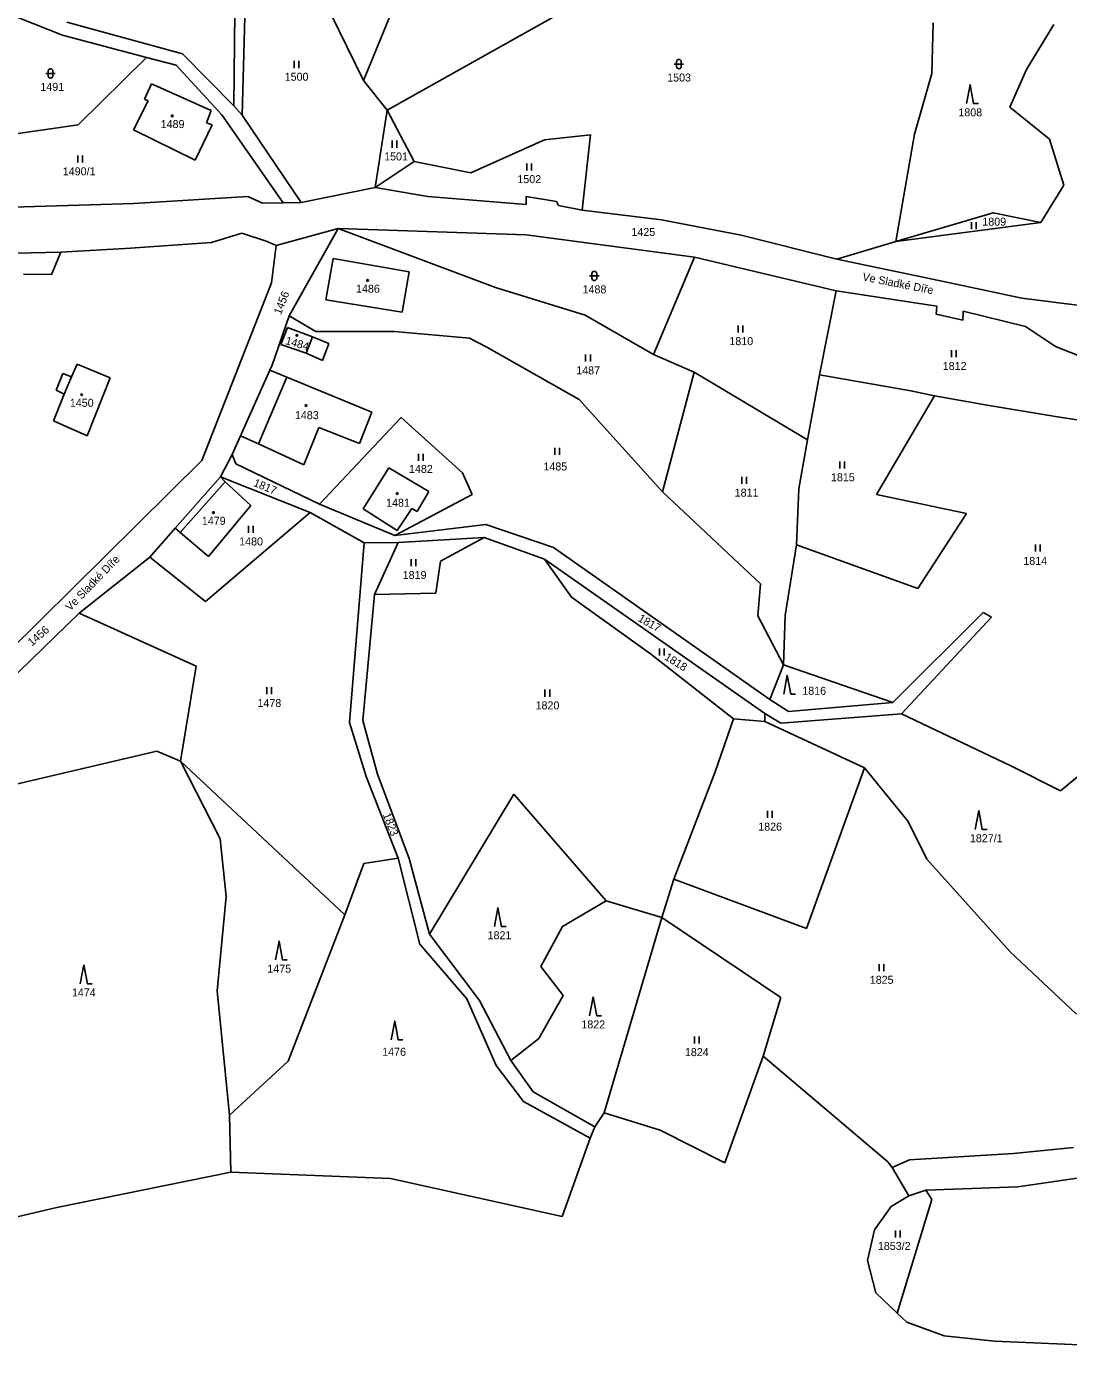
# Model space of a CAD drawing. Extents: x -670359 to -668019, y -978807 to -976674.
# Drawn here: x -669122.6 to -668901.2, y -978796.6 to -978516 of the extents above; entities that cross this region are included whole.
import ezdxf

# ---------------------------------------------------------------- set-up
doc = ezdxf.new("R2010")
doc.units = 0
for name, color, linetype in [('Hranice kat_území', 7, 'Continuous'), ('Hranice parcel', 7, 'Continuous'), ('Parcelní čísla', 7, 'Continuous'), ('Pop  PČ popisy', 7, 'Continuous'), ('Vnitřní kresba', 7, 'Continuous'), ('Značky budov', 7, 'Continuous'), ('Značky kultur', 7, 'Continuous')]:
    doc.layers.add(name, color=color, linetype=linetype)

msp = doc.modelspace()

# ---------------------------------------------------------------- linework, layer by layer
at = {"layer": 'Hranice kat_území'}
for points in [[(-668974.22, -978757.37), (-668966.07, -978734.72)], [(-668966.07, -978734.72), (-668939.56, -978757.11)], [(-669001.78, -978749.69), (-668999.81, -978746.76)], [(-668999.81, -978746.76), (-668987.95, -978750.41)], [(-669002.79, -978752.15), (-669001.78, -978749.69)], [(-668987.95, -978750.41), (-668974.22, -978757.37)], [(-669008.76, -978768.77), (-669002.79, -978752.15)], [(-669116.14, -978766.86), (-669079.11, -978759.37)], [(-669079.11, -978759.37), (-669045.2, -978760.68)], [(-668939.56, -978757.11), (-668938.62, -978758.32)], [(-668938.62, -978758.32), (-668935.12, -978764.38)], [(-669045.2, -978760.68), (-669008.76, -978768.77)], [(-668935.12, -978764.38), (-668938.85, -978766.64)], [(-669129.14, -978769.92), (-669116.14, -978766.86)], [(-668938.85, -978766.64), (-668942.37, -978771.62)], [(-668942.37, -978771.62), (-668943.85, -978778.07)], [(-668943.85, -978778.07), (-668942.12, -978784.98)], [(-668942.12, -978784.98), (-668937.55, -978789.26)], [(-668935.51, -978791.17), (-668937.55, -978789.26)], [(-668935.51, -978791.17), (-668927.63, -978794.11)], [(-668927.63, -978794.11), (-668916.93, -978795.26)], [(-668916.93, -978795.26), (-668885.55, -978796.6)]]:
    msp.add_lwpolyline(points, dxfattribs=at)
at = {"layer": 'Hranice parcel'}
for points in [[(-669050.94, -978527.45), (-669069.9, -978488.77)], [(-669037.87, -978495.52), (-669050.94, -978527.45)], [(-669078.25, -978506.04), (-669078.53, -978532.83)], [(-669075.93, -978506.06), (-669076.71, -978534.85)], [(-669132.89, -978510.73), (-669114.87, -978517.8)], [(-669113.97, -978515.09), (-669089.38, -978521.76)], [(-669008.9, -978513.02), (-669045.91, -978533.73)], [(-668929.94, -978515.21), (-668930.2, -978525.93)], [(-669114.87, -978517.8), (-669097.05, -978522.55)], [(-668910.1, -978525.08), (-668904.33, -978515.58)], [(-669111.55, -978536.87), (-669097.05, -978522.55)], [(-669097.05, -978522.55), (-669090.77, -978524.22)], [(-669089.38, -978521.76), (-669078.53, -978532.83)], [(-669090.77, -978524.22), (-669081.03, -978534.72)], [(-668930.2, -978525.93), (-668933.87, -978538.82)], [(-668913.68, -978533.1), (-668910.1, -978525.08)], [(-669097.49, -978531.43), (-669096.01, -978528.16)], [(-669096.01, -978528.16), (-669083.35, -978533.82)], [(-669045.91, -978533.73), (-669050.94, -978527.45)], [(-669099.8, -978537.96), (-669096.69, -978531.75)], [(-669096.69, -978531.75), (-669097.49, -978531.43)], [(-669083.35, -978533.82), (-669084.29, -978536.41)], [(-669081.03, -978534.72), (-669068.02, -978553.42)], [(-669078.53, -978532.83), (-669076.71, -978534.85)], [(-669076.71, -978534.85), (-669064.18, -978553.38)], [(-669048.49, -978550.2), (-669045.91, -978533.73)], [(-669045.91, -978533.73), (-669040.18, -978544.63)], [(-668905.23, -978539.89), (-668913.68, -978533.1)], [(-669125.82, -978538.9), (-669111.55, -978536.87)], [(-669083.1, -978536.9), (-669086.74, -978544.38)], [(-669084.29, -978536.41), (-669083.1, -978536.9)], [(-669086.74, -978544.38), (-669099.8, -978537.96)], [(-669028.14, -978547.08), (-669012.49, -978540.08)], [(-669012.49, -978540.08), (-669002.7, -978538.97)], [(-669002.7, -978538.97), (-669004.5, -978555.02)], [(-668933.87, -978538.82), (-668937.86, -978561.63)], [(-668902.2, -978549.7), (-668905.23, -978539.89)], [(-669040.18, -978544.63), (-669048.49, -978550.2)], [(-669040.18, -978544.63), (-669028.14, -978547.08)], [(-669048.49, -978550.2), (-669064.18, -978553.38)], [(-669037.27, -978552.07), (-669048.49, -978550.2)], [(-668907.06, -978557.61), (-668902.2, -978549.7)], [(-669099.72, -978553.56), (-669137.18, -978554.7)], [(-669075.53, -978552.06), (-669099.72, -978553.56)], [(-669072.43, -978553.53), (-669075.53, -978552.06)], [(-669068.02, -978553.42), (-669072.43, -978553.53)], [(-669064.18, -978553.38), (-669068.02, -978553.42)], [(-669016.4, -978553.82), (-669037.27, -978552.07)], [(-669016.38, -978552.06), (-669016.4, -978553.82)], [(-669009.99, -978553.17), (-669016.38, -978552.06)], [(-669009.51, -978553.97), (-669009.99, -978553.17)], [(-669004.5, -978555.02), (-669009.51, -978553.97)], [(-669004.5, -978555.02), (-668987.68, -978557.05)], [(-668970.7, -978560.28), (-668987.68, -978557.05)], [(-668937.86, -978561.63), (-668917.19, -978555.59)], [(-668917.19, -978555.59), (-668907.06, -978557.61)], [(-669076.82, -978559.88), (-669083.24, -978561.89)], [(-669071.39, -978561.62), (-669076.82, -978559.88)], [(-669056.35, -978558.88), (-669069.48, -978562.52)], [(-669056.35, -978558.88), (-669066.76, -978577.43)], [(-669016.38, -978560.22), (-669056.35, -978558.88)], [(-669056.35, -978558.88), (-669022.91, -978571.42)], [(-668937.86, -978561.63), (-668907.06, -978557.61)], [(-669083.24, -978561.89), (-669100.46, -978563.07)], [(-669069.48, -978562.52), (-669071.39, -978561.62)], [(-669069.48, -978562.52), (-669070.52, -978570.43)], [(-668980.66, -978564.96), (-669016.38, -978560.22)], [(-668950.41, -978565.41), (-668970.7, -978560.28)], [(-668950.41, -978565.41), (-668937.86, -978561.63)], [(-669115.28, -978563.95), (-669124.89, -978564.16)], [(-669100.46, -978563.07), (-669115.28, -978563.95)], [(-669058.96, -978574.07), (-669057.42, -978565.29)], [(-669057.42, -978565.29), (-669041.28, -978568.11)], [(-668980.66, -978564.96), (-668989.34, -978585.68)], [(-668950.53, -978572.13), (-668980.66, -978564.96)], [(-668927.36, -978570.21), (-668950.41, -978565.41)], [(-669041.28, -978568.11), (-669042.73, -978576.65)], [(-669070.52, -978570.43), (-669085.33, -978608.18)], [(-669022.91, -978571.42), (-669003.84, -978577.31)], [(-668911.1, -978573.7), (-668927.36, -978570.21)], [(-669042.73, -978576.65), (-669058.96, -978574.07)], [(-668950.53, -978572.13), (-668954.08, -978589.98)], [(-668929.14, -978575.38), (-668950.53, -978572.13)], [(-668898.72, -978575.28), (-668911.1, -978573.7)], [(-668929.32, -978577.06), (-668929.14, -978575.38)], [(-668923.55, -978576.44), (-668923.66, -978578.36)], [(-668910.32, -978579.71), (-668923.55, -978576.44)], [(-669066.76, -978577.43), (-669070.39, -978587.95)], [(-669066.76, -978577.43), (-669061.11, -978580.77)], [(-669003.84, -978577.31), (-668989.34, -978585.68)], [(-668923.66, -978578.36), (-668929.32, -978577.06)], [(-668903.91, -978583.99), (-668910.32, -978579.71)], [(-669068.5, -978583.53), (-669067.1, -978579.94)], [(-669067.1, -978579.94), (-669061.76, -978581.88)], [(-669061.76, -978581.88), (-669058.34, -978583.31)], [(-669061.11, -978580.77), (-669044.38, -978580.79)], [(-669044.38, -978580.79), (-669028.46, -978582.16)], [(-669028.46, -978582.16), (-669024.72, -978584.12)], [(-669063.16, -978585.39), (-669068.5, -978583.53)], [(-669063.16, -978585.39), (-669059.69, -978586.9)], [(-669058.34, -978583.31), (-669059.69, -978586.9)], [(-669024.72, -978584.12), (-669005.15, -978595.21)], [(-668897.87, -978586.33), (-668903.91, -978583.99)], [(-669113, -978590.37), (-669111.77, -978587.74)], [(-669111.77, -978587.74), (-669104.76, -978590.62)], [(-669070.39, -978587.95), (-669070.84, -978588.96)], [(-668989.34, -978585.68), (-668980.68, -978589.43)], [(-669116.23, -978593.21), (-669114.83, -978589.71)], [(-669114.83, -978589.71), (-669113, -978590.37)], [(-669104.76, -978590.62), (-669109.69, -978602.96)], [(-669070.84, -978588.96), (-669077.06, -978602.9)], [(-669070.84, -978588.96), (-669067.21, -978590.46)], [(-669067.21, -978590.46), (-669049.2, -978597.93)], [(-668980.68, -978589.43), (-668987.45, -978614.83)], [(-668956.6, -978603.78), (-668980.68, -978589.43)], [(-668954.08, -978589.98), (-668956.6, -978603.78)], [(-668934.65, -978593.36), (-668954.08, -978589.98)], [(-669114.56, -978594.11), (-669116.23, -978593.21)], [(-668929.62, -978594.41), (-668934.65, -978593.36)], [(-669116.78, -978599.76), (-669114.56, -978594.11)], [(-669005.15, -978595.21), (-668987.45, -978614.83)], [(-668929.62, -978594.41), (-668941.99, -978615.39)], [(-668918.45, -978596.45), (-668929.62, -978594.41)], [(-668903.93, -978598.79), (-668918.45, -978596.45)], [(-669060.29, -978617.45), (-669042.97, -978599.04)], [(-669049.2, -978597.93), (-669051.83, -978604.54)], [(-669042.97, -978599.04), (-669029.94, -978610.79)], [(-668890.24, -978600.95), (-668903.93, -978598.79)], [(-669109.69, -978602.96), (-669116.78, -978599.76)], [(-669060.44, -978601.17), (-669063.65, -978609.06)], [(-669051.83, -978604.54), (-669060.44, -978601.17)], [(-669077.06, -978602.9), (-669078.83, -978606.89)], [(-669073.29, -978604.63), (-669077.06, -978602.9)], [(-669063.65, -978609.06), (-669073.29, -978604.63)], [(-668956.6, -978603.78), (-668958.46, -978614.22)], [(-669078.83, -978606.89), (-669081.37, -978611.66)], [(-669078.83, -978606.89), (-669078.05, -978608.9)], [(-669085.33, -978608.18), (-669147.05, -978669.18)], [(-669078.05, -978608.9), (-669060.29, -978617.45)], [(-669051.02, -978618.47), (-669045.56, -978609.73)], [(-669045.56, -978609.73), (-669037.05, -978614.78)], [(-669081.37, -978611.66), (-669090.98, -978622.57)], [(-669080.34, -978612.72), (-669081.37, -978611.66)], [(-669081.37, -978611.66), (-669062.31, -978619.23)], [(-669074.87, -978617.73), (-669080.34, -978612.72)], [(-669029.94, -978610.79), (-669027.88, -978615.4)], [(-669027.88, -978615.4), (-669044.28, -978624.09)], [(-669037.05, -978614.78), (-669039.58, -978618.99)], [(-668966.65, -978634.4), (-668987.45, -978614.83)], [(-668958.46, -978614.22), (-668958.99, -978626.05)], [(-668941.99, -978615.39), (-668922.85, -978619.41)], [(-669083.87, -978628.59), (-669074.87, -978617.73)], [(-669060.29, -978617.45), (-669044.28, -978624.09)], [(-669043.79, -978623.05), (-669051.02, -978618.47)], [(-669040.7, -978618.35), (-669043.79, -978623.05)], [(-669039.58, -978618.99), (-669040.7, -978618.35)], [(-669062.31, -978619.23), (-669084.53, -978638.1)], [(-669050.79, -978625.63), (-669062.31, -978619.23)], [(-669024.95, -978621.77), (-669044.28, -978624.09)], [(-669010.62, -978626.66), (-669024.95, -978621.77)], [(-668922.85, -978619.41), (-668933.21, -978635.39)], [(-669090.98, -978622.57), (-669096.38, -978628.7)], [(-669090.98, -978622.57), (-669089.9, -978623.49)], [(-669089.9, -978623.49), (-669083.87, -978628.59)], [(-669043.59, -978625.6), (-669025.31, -978624.56)], [(-669025.31, -978624.56), (-669034.6, -978629.52)], [(-669012.51, -978629.11), (-669025.31, -978624.56)], [(-669050.79, -978625.63), (-669053.93, -978663.82)], [(-669043.59, -978625.6), (-669050.79, -978625.63)], [(-669048.65, -978636.63), (-669043.59, -978625.6)], [(-668964.6, -978658.91), (-669010.62, -978626.66)], [(-668958.99, -978626.05), (-668961.37, -978641.07)], [(-668933.21, -978635.39), (-668958.99, -978626.05)], [(-669096.38, -978628.7), (-669111.37, -978640.61)], [(-669084.53, -978638.1), (-669096.38, -978628.7)], [(-669034.6, -978629.52), (-669035.6, -978636.38)], [(-668965.69, -978661.93), (-669012.51, -978629.11)], [(-669006.8, -978637.21), (-669012.51, -978629.11)], [(-668967.17, -978641.19), (-668966.65, -978634.4)], [(-669048.65, -978636.63), (-669051.12, -978663.39)], [(-669035.6, -978636.38), (-669048.65, -978636.63)], [(-668989.96, -978649.27), (-669006.8, -978637.21)], [(-669111.37, -978640.61), (-669155.12, -978683.09)], [(-669111.37, -978640.61), (-669086.51, -978651.84)], [(-668961.75, -978651.6), (-668967.17, -978641.19)], [(-668961.37, -978641.07), (-668961.75, -978651.6)], [(-668919.29, -978640.43), (-668938.52, -978659.61)], [(-668936.64, -978661.96), (-668917.55, -978641.42)], [(-668917.55, -978641.42), (-668919.29, -978640.43)], [(-668972.35, -978663.01), (-668989.96, -978649.27)], [(-669086.51, -978651.84), (-669089.85, -978672.04)], [(-668964.6, -978658.91), (-668961.75, -978651.6)], [(-668938.52, -978659.61), (-668961.75, -978651.6)], [(-668960.64, -978661.46), (-668964.6, -978658.91)], [(-668938.52, -978659.61), (-668960.64, -978661.46)], [(-669053.93, -978663.82), (-669050.36, -978675.32)], [(-669051.12, -978663.39), (-669047.95, -978674.8)], [(-668972.35, -978663.01), (-668976.23, -978674.31)], [(-668965.72, -978663.61), (-668972.35, -978663.01)], [(-668965.69, -978661.93), (-668965.72, -978663.61)], [(-668965.72, -978663.61), (-668944.52, -978673.42)], [(-668962.28, -978663.99), (-668965.69, -978661.93)], [(-668936.64, -978661.96), (-668962.28, -978663.99)], [(-668913.45, -978673.01), (-668936.64, -978661.96)], [(-669094.87, -978669.91), (-669132.02, -978678.62)], [(-669089.85, -978672.04), (-669094.87, -978669.91)], [(-669089.85, -978672.04), (-669081.38, -978688.53)], [(-669089.85, -978672.04), (-669054.9, -978704.7)], [(-669047.95, -978674.8), (-669041.22, -978692.68)], [(-668976.23, -978674.31), (-668985.03, -978697.11)], [(-668944.52, -978673.42), (-668956.87, -978707.6)], [(-668944.52, -978673.42), (-668935.27, -978684.87)], [(-668902.9, -978678.32), (-668913.45, -978673.01)], [(-668898.03, -978674.32), (-668902.9, -978678.32)], [(-669050.36, -978675.32), (-669043.62, -978692.64)], [(-669019.05, -978679.07), (-669036.93, -978708.75)], [(-668999.43, -978701.73), (-669019.05, -978679.07)], [(-668935.27, -978684.87), (-668931.25, -978692.86)], [(-669081.38, -978688.53), (-669080.14, -978700.78)], [(-669050.9, -978693.8), (-669054.9, -978704.7)], [(-669043.62, -978692.64), (-669050.9, -978693.8)], [(-669038.97, -978710.88), (-669043.62, -978692.64)], [(-669041.22, -978692.68), (-669036.93, -978708.75)], [(-668931.25, -978692.86), (-668913.58, -978712.53)], [(-668985.03, -978697.11), (-668987.57, -978705.22)], [(-668956.87, -978707.6), (-668985.03, -978697.11)], [(-669080.14, -978700.78), (-669082.04, -978720.84)], [(-669008.65, -978707.17), (-668999.43, -978701.73)], [(-668987.57, -978705.22), (-668999.43, -978701.73)], [(-669054.9, -978704.7), (-669066.94, -978735.74)], [(-668987.57, -978705.22), (-668999.81, -978746.76)], [(-668987.57, -978705.22), (-668962.33, -978722.23)], [(-669036.93, -978708.75), (-669026.29, -978722.86)], [(-669013.28, -978715.65), (-669008.65, -978707.17)], [(-669029.01, -978722.49), (-669038.97, -978710.88)], [(-668913.58, -978712.53), (-668899.48, -978725.81)], [(-669008.51, -978721.81), (-669013.28, -978715.65)], [(-669082.04, -978720.84), (-669079.46, -978747.2)], [(-669022.77, -978736.68), (-669029.01, -978722.49)], [(-669026.29, -978722.86), (-669019.63, -978735.62)], [(-669013.71, -978730.92), (-669008.51, -978721.81)], [(-668962.33, -978722.23), (-668966.07, -978734.72)], [(-669019.63, -978735.62), (-669013.71, -978730.92)], [(-669066.94, -978735.74), (-669079.46, -978747.2)], [(-669016.98, -978744.3), (-669022.77, -978736.68)], [(-669019.63, -978735.62), (-669014.94, -978742.26)], [(-669014.94, -978742.26), (-669001.78, -978749.69)], [(-669002.79, -978752.15), (-669016.98, -978744.3)], [(-669079.46, -978747.2), (-669079.11, -978759.37)], [(-668934.99, -978756.71), (-668912.88, -978755.34)], [(-668912.88, -978755.34), (-668900.13, -978754.12)], [(-668934.99, -978756.71), (-668938.62, -978758.32)], [(-668891.55, -978759.47), (-668911.96, -978762.42)], [(-668931.46, -978763.13), (-668935.12, -978764.38)], [(-668911.96, -978762.42), (-668931.46, -978763.13)], [(-668931.46, -978763.13), (-668930.24, -978765.16)], [(-668930.24, -978765.16), (-668937.55, -978789.26)]]:
    msp.add_lwpolyline(points, dxfattribs=at)
at = {"layer": 'Vnitřní kresba'}
for points in [[(-669117.25, -978568.65), (-669115.28, -978563.95)], [(-669123.18, -978568.58), (-669117.25, -978568.65)], [(-669063.16, -978585.39), (-669061.76, -978581.88)], [(-669114.56, -978594.11), (-669113, -978590.37)], [(-669073.29, -978604.63), (-669067.21, -978590.46)], [(-669089.9, -978623.49), (-669080.34, -978612.72)]]:
    msp.add_lwpolyline(points, dxfattribs=at)
at = {"layer": 'Značky budov'}
for centre in [(-669091.59, -978534.96), (-669050.09, -978569.92), (-669065.11, -978581.58), (-669110.84, -978594.17), (-669063.18, -978596.5), (-669043.8, -978615.19), (-669082.84, -978619.23)]:
    msp.add_circle(centre, 0.175, dxfattribs=at)
at = {"layer": 'Značky kultur'}
for p, q in [((-669065.7, -978523.3), (-669065.7, -978524.8)), ((-669064.7, -978524.8), (-669064.7, -978523.3)), ((-668984.44, -978523.47), (-668984.44, -978524.47)), ((-668983.44, -978523.47), (-668983.44, -978524.47)), ((-669118.43, -978525.95), (-669116.43, -978525.95)), ((-669117.93, -978525.45), (-669117.93, -978526.45)), ((-669116.93, -978525.45), (-669116.93, -978526.45)), ((-668984.94, -978523.97), (-668982.94, -978523.97)), ((-669044.89, -978540.23), (-669044.89, -978541.73)), ((-669043.89, -978541.73), (-669043.89, -978540.23)), ((-669111.66, -978543.4), (-669111.66, -978544.9)), ((-669110.66, -978544.9), (-669110.66, -978543.4)), ((-669016.27, -978545.05), (-669016.27, -978546.55)), ((-669015.27, -978546.55), (-669015.27, -978545.05)), ((-668921.81, -978557.55), (-668921.81, -978559.05)), ((-668920.81, -978559.05), (-668920.81, -978557.55)), ((-669002.42, -978568.47), (-669002.42, -978569.47)), ((-669001.42, -978568.47), (-669001.42, -978569.47)), ((-669002.92, -978568.97), (-669000.92, -978568.97)), ((-668971.37, -978579.47), (-668971.37, -978580.97)), ((-668970.37, -978580.97), (-668970.37, -978579.47)), ((-668926.04, -978584.74), (-668926.04, -978586.24)), ((-668925.04, -978586.24), (-668925.04, -978584.74)), ((-669003.76, -978585.67), (-669003.76, -978587.17)), ((-669002.76, -978587.17), (-669002.76, -978585.67)), ((-669039.29, -978606.74), (-669039.29, -978608.24)), ((-669038.29, -978608.24), (-669038.29, -978606.74)), ((-669010.3, -978605.45), (-669010.3, -978606.95)), ((-669009.3, -978606.95), (-669009.3, -978605.45)), ((-668949.79, -978608.38), (-668949.79, -978609.88)), ((-668948.79, -978609.88), (-668948.79, -978608.38)), ((-668970.57, -978611.66), (-668970.57, -978613.16)), ((-668969.57, -978613.16), (-668969.57, -978611.66)), ((-669075.37, -978622.02), (-669075.37, -978623.52)), ((-669074.37, -978623.52), (-669074.37, -978622.02)), ((-668908.18, -978626), (-668908.18, -978627.5)), ((-668907.18, -978627.5), (-668907.18, -978626)), ((-669040.81, -978629.14), (-669040.81, -978630.64)), ((-669039.81, -978630.64), (-669039.81, -978629.14)), ((-668988.06, -978648.07), (-668988.06, -978649.57)), ((-668987.06, -978649.57), (-668987.06, -978648.07)), ((-669071.48, -978656.33), (-669071.48, -978657.83)), ((-669070.48, -978657.83), (-669070.48, -978656.33)), ((-669012.4, -978656.84), (-669012.4, -978658.34)), ((-669011.4, -978658.34), (-669011.4, -978656.84)), ((-668965.14, -978682.6), (-668965.14, -978684.1)), ((-668964.14, -978684.1), (-668964.14, -978682.6)), ((-668941.4, -978715.13), (-668941.4, -978716.63)), ((-668940.4, -978716.63), (-668940.4, -978715.13)), ((-668980.64, -978730.49), (-668980.64, -978731.99)), ((-668979.64, -978731.99), (-668979.64, -978730.49)), ((-668937.94, -978771.72), (-668937.94, -978773.22)), ((-668936.94, -978773.22), (-668936.94, -978771.72))]:
    msp.add_line(p, q, dxfattribs=at)
for points in [[(-668922.83, -978532.37), (-668922.08, -978528.37), (-668921.33, -978532.37), (-668920.33, -978532.37)], [(-668961.68, -978657.79), (-668960.93, -978653.79), (-668960.18, -978657.79), (-668959.18, -978657.79)], [(-668920.99, -978686.53), (-668920.24, -978682.53), (-668919.49, -978686.53), (-668918.49, -978686.53)], [(-669023.16, -978707.17), (-669022.41, -978703.17), (-669021.66, -978707.17), (-669020.66, -978707.17)], [(-669069.64, -978714.27), (-669068.89, -978710.27), (-669068.14, -978714.27), (-669067.14, -978714.27)], [(-669111.12, -978719.32), (-669110.37, -978715.32), (-669109.62, -978719.32), (-669108.62, -978719.32)], [(-669002.92, -978726.1), (-669002.17, -978722.1), (-669001.42, -978726.1), (-669000.42, -978726.1)], [(-669045.07, -978731.26), (-669044.32, -978727.26), (-669043.57, -978731.26), (-669042.57, -978731.26)]]:
    msp.add_lwpolyline(points, dxfattribs=at)
for centre in [(-669091.59, -978534.96), (-669050.09, -978569.92), (-669065.11, -978581.58), (-669110.84, -978594.17), (-669063.18, -978596.5), (-669043.8, -978615.19), (-669082.84, -978619.23)]:
    msp.add_circle(centre, 0.175, dxfattribs=at)
for centre, start, end in [((-668983.94, -978523.47), 0, 180), ((-669117.43, -978525.45), 0, 180), ((-669117.43, -978526.45), 180, 0), ((-668983.94, -978524.47), 180, 0), ((-669001.92, -978568.47), 0, 180), ((-669001.92, -978569.47), 180, 0)]:
    msp.add_arc(centre, 0.5, start, end, dxfattribs=at)

# ---------------------------------------------------------------- texts
at = {"layer": 'Parcelní čísla'}
for s, p in [('1500', (-669067.7, -978527.5)), ('1503', (-668986.44, -978527.67)), ('1491', (-669119.61, -978529.65)), ('1808', (-668924.58, -978535.07)), ('1489', (-669094.05, -978537.56)), ('1501', (-669046.57, -978544.43)), ('1490/1', (-669114.84, -978547.6)), ('1502', (-669018.27, -978549.25)), ('1809', (-668919.49, -978558.29)), ('1425', (-668994.04, -978560.48)), ('1486', (-669052.55, -978572.52)), ('1488', (-669004.42, -978572.67)), ('1810', (-668973.23, -978583.67)), ('1487', (-669005.76, -978589.87)), ('1812', (-668927.9, -978588.94)), ('1450', (-669113.34, -978596.77)), ('1483', (-669065.53, -978599.39)), ('1482', (-669041.29, -978610.81)), ('1485', (-669012.73, -978610.29)), ('1815', (-668951.65, -978612.58)), ('1481', (-669046.16, -978617.99)), ('1811', (-668972.11, -978615.86)), ('1479', (-669085.3, -978621.83)), ('1480', (-669077.37, -978626.22)), ('1814', (-668910.78, -978630.34)), ('1819', (-669042.63, -978633.34)), ('1816', (-668957.74, -978657.94)), ('1478', (-669073.48, -978660.53)), ('1820', (-669014.4, -978661.04)), ('1826', (-668967.1, -978686.8)), ('1827/1', (-668922.13, -978689.26)), ('1821', (-669024.59, -978709.87)), ('1475', (-669071.39, -978716.97)), ('1825', (-668943.4, -978719.33)), ('1474', (-669112.91, -978722.02)), ('1822', (-669004.67, -978728.8)), ('1476', (-669046.99, -978734.62)), ('1824', (-668982.68, -978734.69)), ('1853/2', (-668941.68, -978775.86))]:
    msp.add_text(s, height=1.7, dxfattribs=at).set_placement(p)
for s, rotation, p in [('1456', 68.5032, (-669068.52, -978577.32)), ('1484', 344.2192, (-669067.68, -978583.43)), ('1817', 337.249, (-669074.5, -978613.52)), ('1817', 330.3956, (-668992.79, -978642.18)), ('1456', 40.8503, (-669121.39, -978647.71)), ('1818', 328.2665, (-668987.16, -978650.35)), ('1823', 291.2092, (-669046.88, -978683.4))]:
    msp.add_text(s, height=1.7, rotation=rotation, dxfattribs=at).set_placement(p)
at = {"layer": 'Pop  PČ popisy'}
for rotation, p in [(348.8975, (-668945.06, -978569.92)), (45.7649, (-669113.26, -978640.24))]:
    msp.add_text('Ve Sladké Díře', height=1.7, rotation=rotation, dxfattribs=at).set_placement(p)

doc.saveas('drawing.dxf')
